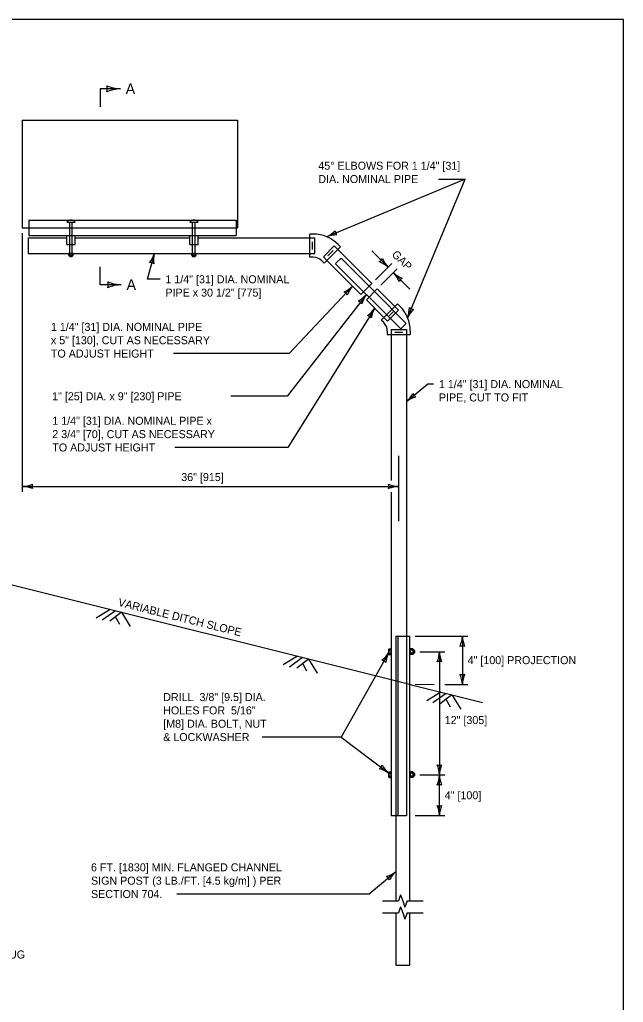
# Model space of a CAD drawing. Extents: x 49991.4 to 50021, y 49987.6 to 50011.4.
# Drawn here: x 50004.09 to 50008.61, y 50003.9 to 50011.26 of the extents above; entities that cross this region are included whole.
import ezdxf

# ---------------------------------------------------------------- set-up
doc = ezdxf.new("R2010")
doc.units = 0
for name, color, linetype in [('Level 1', 7, 'Continuous'), ('Level 2', 7, 'Continuous'), ('Level 3', 7, 'Continuous'), ('Level 4', 7, 'Continuous'), ('Level 5', 7, 'Continuous'), ('Level 6', 7, 'Continuous')]:
    doc.layers.add(name, color=color, linetype=linetype)

msp = doc.modelspace()

# ---------------------------------------------------------------- linework, layer by layer
at = {"layer": 'Level 1'}
for p, q in [((50004.1085, 50010.5093), (50004.1085, 50009.7029)), ((50004.1085, 50010.5093), (50005.7213, 50010.5093)), ((50005.7213, 50010.5093), (50005.7213, 50009.7029)), ((50004.1085, 50009.7029), (50005.7213, 50009.7029)), ((50004.1564, 50009.7029), (50004.1564, 50009.6453)), ((50004.4424, 50009.7455), (50004.5041, 50009.7455)), ((50005.364, 50009.7455), (50005.4257, 50009.7455)), ((50005.7116, 50009.7029), (50005.7116, 50009.6453)), ((50004.1517, 50009.6262), (50004.1517, 50009.511)), ((50004.1517, 50009.6262), (50004.442, 50009.6262)), ((50004.1564, 50009.6453), (50005.7116, 50009.6453)), ((50004.442, 50009.5782), (50004.442, 50009.6453)), ((50004.5045, 50009.5782), (50004.5045, 50009.6453)), ((50004.5045, 50009.6262), (50005.3637, 50009.6262)), ((50005.3637, 50009.5782), (50005.3637, 50009.6453)), ((50005.4261, 50009.5782), (50005.4261, 50009.6453)), ((50005.4261, 50009.6262), (50006.2641, 50009.6262)), ((50006.2641, 50009.4822), (50006.2641, 50009.655)), ((50006.2902, 50009.655), (50006.2641, 50009.655)), ((50004.442, 50009.5782), (50004.5045, 50009.5782)), ((50005.3637, 50009.5782), (50005.4261, 50009.5782)), ((50006.3722, 50009.4374), (50006.4943, 50009.5597)), ((50006.4739, 50009.5393), (50006.7285, 50009.2847)), ((50006.4757, 50009.5782), (50006.4943, 50009.5597)), ((50004.1517, 50009.511), (50006.2641, 50009.511)), ((50004.4566, 50009.4953), (50004.4566, 50009.5106)), ((50004.4899, 50009.5106), (50004.4566, 50009.5106)), ((50004.4566, 50009.4953), (50004.4589, 50009.4939)), ((50004.4589, 50009.5106), (50004.4589, 50009.511)), ((50004.4732, 50009.511), (50004.4589, 50009.511)), ((50004.4876, 50009.4939), (50004.4589, 50009.4939)), ((50004.4637, 50009.511), (50004.4637, 50009.5123)), ((50004.4637, 50009.4867), (50004.4637, 50009.4939)), ((50004.4829, 50009.4891), (50004.4637, 50009.4891)), ((50004.4637, 50009.4867), (50004.466, 50009.4843)), ((50004.4649, 50009.4951), (50004.4649, 50009.5106)), ((50004.4804, 50009.4915), (50004.466, 50009.4915)), ((50004.4804, 50009.4867), (50004.466, 50009.4867)), ((50004.4804, 50009.4843), (50004.466, 50009.4843)), ((50004.4732, 50009.511), (50004.4732, 50009.511)), ((50004.4876, 50009.511), (50004.4732, 50009.511)), ((50004.4829, 50009.4867), (50004.4804, 50009.4843)), ((50004.4817, 50009.4951), (50004.4817, 50009.5106)), ((50004.4829, 50009.511), (50004.4829, 50009.5123)), ((50004.4829, 50009.4867), (50004.4829, 50009.4939)), ((50004.4876, 50009.5106), (50004.4876, 50009.511)), ((50004.4899, 50009.4953), (50004.4876, 50009.4939)), ((50004.4899, 50009.4953), (50004.4899, 50009.5106)), ((50005.3782, 50009.4953), (50005.3782, 50009.5106)), ((50005.4115, 50009.5106), (50005.3782, 50009.5106)), ((50005.3782, 50009.4953), (50005.3805, 50009.4939)), ((50005.3805, 50009.5106), (50005.3805, 50009.511)), ((50005.3948, 50009.511), (50005.3805, 50009.511)), ((50005.4092, 50009.4939), (50005.3805, 50009.4939)), ((50005.3853, 50009.511), (50005.3853, 50009.5123)), ((50005.3853, 50009.4867), (50005.3853, 50009.4939)), ((50005.4045, 50009.4891), (50005.3853, 50009.4891)), ((50005.3853, 50009.4867), (50005.3876, 50009.4843)), ((50005.3865, 50009.4951), (50005.3865, 50009.5106)), ((50005.402, 50009.4915), (50005.3876, 50009.4915)), ((50005.402, 50009.4867), (50005.3876, 50009.4867)), ((50005.402, 50009.4843), (50005.3876, 50009.4843)), ((50005.3948, 50009.511), (50005.3948, 50009.511)), ((50005.4092, 50009.511), (50005.3948, 50009.511)), ((50005.4045, 50009.4867), (50005.402, 50009.4843)), ((50005.4033, 50009.4951), (50005.4033, 50009.5106)), ((50005.4045, 50009.511), (50005.4045, 50009.5123)), ((50005.4045, 50009.4867), (50005.4045, 50009.4939)), ((50005.4092, 50009.5106), (50005.4092, 50009.511)), ((50005.4115, 50009.4953), (50005.4092, 50009.4939)), ((50005.4115, 50009.4953), (50005.4115, 50009.5106)), ((50006.2902, 50009.4822), (50006.2641, 50009.4822)), ((50006.3536, 50009.456), (50006.3722, 50009.4374)), ((50006.3926, 50009.4578), (50006.6471, 50009.2033)), ((50006.6471, 50009.2033), (50006.7285, 50009.2847)), ((50006.6878, 50009.1626), (50006.7692, 50009.2439)), ((50006.7082, 50009.2644), (50006.7489, 50009.2237)), ((50006.7692, 50009.2439), (50006.9016, 50009.1117)), ((50006.6674, 50009.2236), (50006.7082, 50009.183)), ((50006.6878, 50009.1626), (50006.8201, 50009.0302)), ((50006.7997, 50009.0098), (50006.922, 50009.1321)), ((50006.9405, 50009.1135), (50006.922, 50009.1321)), ((50006.8183, 50008.9913), (50006.7997, 50009.0098)), ((50006.8445, 50008.928), (50006.8445, 50008.9018)), ((50006.8445, 50008.9018), (50007.0173, 50008.9018)), ((50006.8733, 50008.9018), (50006.8733, 50007.8069)), ((50006.9885, 50008.9018), (50006.9885, 50006.6729)), ((50007.0173, 50008.928), (50007.0173, 50008.9018)), ((50006.8733, 50007.7205), (50006.8733, 50006.315)), ((50003.7136, 50007.1049), (50007.0128, 50006.2801)), ((50004.7673, 50006.8415), (50004.6622, 50006.7767)), ((50004.807, 50006.8316), (50004.7076, 50006.7607)), ((50004.8511, 50006.8205), (50004.7634, 50006.7529)), ((50004.8511, 50006.8205), (50004.9168, 50006.7139)), ((50004.8391, 50006.7284), (50004.8072, 50006.7867)), ((50006.9885, 50006.6729), (50006.9885, 50006.6401)), ((50006.9086, 50006.6401), (50007.0128, 50006.6401)), ((50006.9086, 50006.6401), (50006.9086, 50006.3062)), ((50006.923, 50006.6401), (50006.923, 50006.3026)), ((50007.0128, 50006.2801), (50007.0128, 50006.6401)), ((50006.8582, 50006.5457), (50006.8565, 50006.5429)), ((50006.8565, 50006.507), (50006.8565, 50006.5429)), ((50006.8582, 50006.5041), (50006.8565, 50006.507)), ((50006.8581, 50006.5354), (50006.8733, 50006.5354)), ((50006.8581, 50006.5144), (50006.8733, 50006.5144)), ((50006.8582, 50006.5457), (50006.8733, 50006.5457)), ((50006.8733, 50006.5249), (50006.8733, 50006.5457)), ((50006.8733, 50006.5369), (50006.875, 50006.5369)), ((50006.8733, 50006.5249), (50006.8733, 50006.5249)), ((50006.8733, 50006.5041), (50006.8733, 50006.5249)), ((50006.8733, 50006.5129), (50006.875, 50006.5129)), ((50007.0128, 50006.5369), (50007.0111, 50006.5369)), ((50007.0128, 50006.5129), (50007.0111, 50006.5129)), ((50007.0128, 50006.5489), (50007.0167, 50006.5489)), ((50007.0128, 50006.5489), (50007.0128, 50006.5249)), ((50007.0128, 50006.5249), (50007.0128, 50006.5249)), ((50007.0128, 50006.5249), (50007.0128, 50006.5009)), ((50007.0167, 50006.5489), (50007.0167, 50006.5457)), ((50007.0167, 50006.5457), (50007.0167, 50006.5041)), ((50007.0172, 50006.5429), (50007.0167, 50006.5429)), ((50007.0167, 50006.5249), (50007.0167, 50006.5249)), ((50007.0172, 50006.507), (50007.0167, 50006.507)), ((50007.0364, 50006.5457), (50007.0172, 50006.5457)), ((50007.0172, 50006.5457), (50007.0172, 50006.5041)), ((50007.0364, 50006.5354), (50007.0172, 50006.5354)), ((50007.0364, 50006.5144), (50007.0172, 50006.5144)), ((50007.0364, 50006.5457), (50007.0381, 50006.5429)), ((50007.0364, 50006.5041), (50007.0381, 50006.507)), ((50007.0381, 50006.5429), (50007.0381, 50006.507)), ((50007.047, 50006.5369), (50007.0381, 50006.5369)), ((50007.047, 50006.5129), (50007.0381, 50006.5129)), ((50007.041, 50006.5339), (50007.041, 50006.5159)), ((50007.044, 50006.5369), (50007.044, 50006.5129)), ((50007.047, 50006.5369), (50007.05, 50006.5339)), ((50007.047, 50006.5339), (50007.047, 50006.5159)), ((50007.047, 50006.5129), (50007.05, 50006.5159)), ((50007.05, 50006.5339), (50007.05, 50006.5159)), ((50006.1705, 50006.4907), (50006.0653, 50006.4259)), ((50006.2102, 50006.4807), (50006.1108, 50006.4099)), ((50006.2542, 50006.4698), (50006.1666, 50006.4022)), ((50006.2423, 50006.3777), (50006.2104, 50006.4359)), ((50006.2542, 50006.4698), (50006.32, 50006.3631)), ((50006.8582, 50006.5041), (50006.8733, 50006.5041)), ((50007.0128, 50006.5009), (50007.0167, 50006.5009)), ((50007.0167, 50006.5041), (50007.0167, 50006.5009)), ((50007.0364, 50006.5041), (50007.0172, 50006.5041)), ((50007.0128, 50006.2801), (50007.0255, 50006.277)), ((50007.0255, 50006.277), (50007.5584, 50006.1437)), ((50007.2459, 50006.2218), (50007.1408, 50006.157)), ((50007.2856, 50006.2119), (50007.1862, 50006.1411)), ((50007.3297, 50006.2009), (50007.242, 50006.1333)), ((50007.3177, 50006.1089), (50007.2858, 50006.1671)), ((50007.3297, 50006.2009), (50007.3954, 50006.0943)), ((50006.8582, 50005.624), (50006.8565, 50005.6212)), ((50006.8565, 50005.5854), (50006.8565, 50005.6212)), ((50006.8582, 50005.624), (50006.8733, 50005.624)), ((50006.8733, 50005.6033), (50006.8733, 50005.624)), ((50007.0128, 50005.6273), (50007.0167, 50005.6273)), ((50007.0128, 50005.6273), (50007.0128, 50005.6033)), ((50007.0167, 50005.6273), (50007.0167, 50005.6241)), ((50007.0167, 50005.6241), (50007.0167, 50005.5825)), ((50007.0172, 50005.6213), (50007.0167, 50005.6213)), ((50007.0364, 50005.6241), (50007.0172, 50005.6241)), ((50007.0172, 50005.6241), (50007.0172, 50005.5825)), ((50007.0364, 50005.6241), (50007.0381, 50005.6213)), ((50007.0381, 50005.6213), (50007.0381, 50005.5854)), ((50006.8582, 50005.5825), (50006.8565, 50005.5854)), ((50006.8581, 50005.6138), (50006.8733, 50005.6138)), ((50006.8581, 50005.5928), (50006.8733, 50005.5928)), ((50006.8582, 50005.5825), (50006.8733, 50005.5825)), ((50006.8733, 50005.6153), (50006.875, 50005.6153)), ((50006.8733, 50005.6033), (50006.8733, 50005.6033)), ((50006.8733, 50005.5825), (50006.8733, 50005.6033)), ((50006.8733, 50005.5913), (50006.875, 50005.5913)), ((50007.0128, 50005.6153), (50007.0111, 50005.6153)), ((50007.0128, 50005.5913), (50007.0111, 50005.5913)), ((50007.0128, 50005.6033), (50007.0128, 50005.6033)), ((50007.0128, 50005.6033), (50007.0128, 50005.5793)), ((50007.0128, 50005.5793), (50007.0167, 50005.5793)), ((50007.0167, 50005.6033), (50007.0167, 50005.6033)), ((50007.0172, 50005.5854), (50007.0167, 50005.5854)), ((50007.0167, 50005.5825), (50007.0167, 50005.5793)), ((50007.0364, 50005.6138), (50007.0172, 50005.6138)), ((50007.0364, 50005.5928), (50007.0172, 50005.5928)), ((50007.0364, 50005.5825), (50007.0172, 50005.5825)), ((50007.0364, 50005.5825), (50007.0381, 50005.5854)), ((50007.047, 50005.6153), (50007.0381, 50005.6153)), ((50007.047, 50005.5913), (50007.0381, 50005.5913)), ((50007.041, 50005.6123), (50007.041, 50005.5943)), ((50007.044, 50005.6153), (50007.044, 50005.5913)), ((50007.047, 50005.6153), (50007.05, 50005.6123)), ((50007.047, 50005.6123), (50007.047, 50005.5943)), ((50007.047, 50005.5913), (50007.05, 50005.5943)), ((50007.05, 50005.6123), (50007.05, 50005.5943))]:
    msp.add_line(p, q, dxfattribs=at)
msp.add_lwpolyline([(50008.6146, 50011.2628), (50000.3356, 50011.2628), (50000.3356, 50000.0624), (50008.6146, 50000.0624)], close=True, dxfattribs=at)
for centre, radius, start, end in [((50004.4732, 50009.7214), 0.0392, 38.02497, 141.97503), ((50005.3949, 50009.7214), 0.0392, 38.02497, 141.97503), ((50006.2903, 50009.3927), 0.2623, 45, 90), ((50004.4608, 50009.5011), 0.0072, 234.6726, 304.40523), ((50004.4733, 50009.5227), 0.0288, 253.01489, 286.97814), ((50004.4857, 50009.5011), 0.0072, 235.59477, 305.17175), ((50005.3824, 50009.5011), 0.0072, 234.6726, 304.40523), ((50005.3949, 50009.5227), 0.0288, 253.01489, 286.97814), ((50005.4073, 50009.5011), 0.0072, 235.59477, 305.17175), ((50006.2903, 50009.3927), 0.0895, 45, 90), ((50006.755, 50008.928), 0.2623, 0, 45), ((50006.755, 50008.928), 0.0895, 0, 45), ((50006.8655, 50006.5405), 0.009, 144.6726, 214.40523), ((50006.8925, 50006.5249), 0.036, 163.01489, 196.97814), ((50006.8655, 50006.5093), 0.009, 145.59477, 215.17175), ((50007.029, 50006.5405), 0.009, 325.59477, 35.17175), ((50007.002, 50006.5249), 0.036, 343.01489, 16.97814), ((50007.029, 50006.5093), 0.009, 324.6726, 34.40523), ((50006.8655, 50005.6189), 0.009, 144.6726, 214.40523), ((50007.029, 50005.6189), 0.009, 325.59477, 35.17175), ((50006.8925, 50005.6033), 0.036, 163.01489, 196.97814), ((50006.8655, 50005.5877), 0.009, 145.59477, 215.17175), ((50007.002, 50005.6033), 0.036, 343.01489, 16.97814), ((50007.029, 50005.5877), 0.009, 324.6726, 34.40523)]:
    msp.add_arc(centre, radius, start, end, dxfattribs=at)
at = {"layer": 'Level 3'}
for p, q in [((50007.4278, 50010.0678), (50006.3907, 50009.635)), ((50006.9973, 50009.0284), (50007.4278, 50010.0678)), ((50007.2289, 50010.0678), (50007.4278, 50010.0678)), ((50004.1085, 50009.6629), (50004.1085, 50007.7237)), ((50006.8506, 50009.4069), (50006.728, 50009.5295)), ((50005.0463, 50009.3166), (50005.0983, 50009.511)), ((50006.7567, 50009.3131), (50006.8789, 50009.4352)), ((50006.7975, 50009.2722), (50006.9197, 50009.3944)), ((50005.1412, 50009.3166), (50005.0463, 50009.3166)), ((50007.014, 50009.2435), (50006.8914, 50009.3661)), ((50006.5845, 50009.2659), (50006.108, 50008.7597)), ((50006.6878, 50009.2033), (50006.095, 50008.4396)), ((50006.7503, 50009.1), (50006.1002, 50008.0557)), ((50006.108, 50008.7597), (50005.2411, 50008.7597)), ((50007.1487, 50008.5307), (50006.9885, 50008.3987)), ((50007.192, 50008.5307), (50007.1487, 50008.5307)), ((50006.095, 50008.4396), (50005.673, 50008.4396)), ((50006.1002, 50008.0557), (50005.2515, 50008.0557)), ((50004.1085, 50007.7637), (50006.9309, 50007.7637)), ((50007.0528, 50006.6401), (50007.4475, 50006.6401)), ((50007.4075, 50006.6401), (50007.4075, 50006.28)), ((50006.8565, 50006.5188), (50006.4999, 50005.8847)), ((50007.09, 50006.5242), (50007.2755, 50006.5242)), ((50007.2355, 50006.5242), (50007.2355, 50005.6009)), ((50007.0528, 50006.2801), (50007.1955, 50006.28)), ((50007.2755, 50006.28), (50007.4475, 50006.28)), ((50006.4999, 50005.8847), (50005.9058, 50005.8847)), ((50006.4999, 50005.8847), (50006.8565, 50005.6148)), ((50007.09, 50005.6009), (50007.2755, 50005.6009)), ((50007.2355, 50005.2961), (50007.2355, 50005.6009)), ((50007.0528, 50005.2961), (50007.2755, 50005.2961)), ((50006.9086, 50004.8754), (50006.7083, 50004.7082)), ((50006.7083, 50004.7082), (50005.2679, 50004.7082))]:
    msp.add_line(p, q, dxfattribs=at)
for centre, radius, start, end in [((50004.8556, 50011.0408), 0.2964, 247.45601, 267.63952), ((50004.6724, 50010.7446), 0.073, 342.13882, 17.86118), ((50004.8587, 50010.4343), 0.3107, 92.82731, 112.07716), ((50006.2905, 50009.8453), 0.233, 295.47894, 314.72879), ((50006.509, 50009.6844), 0.0548, 184.79045, 220.51281), ((50006.4678, 50009.4265), 0.2223, 90.10764, 110.29115), ((50004.886, 50009.5772), 0.2223, 322.48314, 342.66664), ((50005.326, 50009.462), 0.233, 167.85444, 187.10429), ((50006.7599, 50009.4975), 0.0548, 297.17386, 332.89623), ((50007.014, 50009.5576), 0.2223, 202.49106, 222.67456), ((50005.0651, 50009.3871), 0.0548, 57.16594, 92.88831), ((50006.6943, 50009.2341), 0.233, 47.86236, 67.11221), ((50006.7278, 50009.2155), 0.2223, 22.45601, 42.63952), ((50007.0478, 50009.5388), 0.233, 227.82731, 247.07716), ((50006.9821, 50009.2755), 0.0548, 117.13882, 152.86118), ((50004.8622, 50009.572), 0.2964, 247.45601, 267.63952), ((50004.679, 50009.2758), 0.073, 342.13882, 17.86118), ((50004.8653, 50008.9655), 0.3107, 92.82731, 112.07716), ((50006.4278, 50009.4235), 0.2223, 294.66093, 314.84444), ((50006.7631, 50009.1162), 0.233, 140.03223, 159.28208), ((50006.4974, 50009.1718), 0.0548, 29.34374, 65.0661), ((50006.5184, 50009.3472), 0.2223, 299.47187, 319.65538), ((50006.8783, 50009.0691), 0.233, 144.84317, 164.09302), ((50006.6089, 50009.1022), 0.0548, 34.15468, 69.87704), ((50006.5658, 50009.224), 0.2223, 305.91704, 326.10055), ((50006.9547, 50008.9881), 0.233, 151.28834, 170.53819), ((50006.7779, 50009.1069), 0.233, 340.32889, 359.57874), ((50007.199, 50008.935), 0.2223, 134.95759, 155.1411), ((50007.0464, 50009.1469), 0.0548, 229.6404, 265.36276), ((50006.6833, 50008.9908), 0.0548, 40.59985, 76.32221), ((50006.8316, 50008.571), 0.233, 312.31816, 331.56801), ((50007.1227, 50008.2214), 0.2223, 106.94686, 127.13036), ((50007.0874, 50008.4802), 0.0548, 201.62966, 237.35203), ((50004.097, 50007.9964), 0.233, 272.82731, 292.07716), ((50004.0993, 50007.5416), 0.2223, 67.45601, 87.63952), ((50004.2367, 50007.7637), 0.0548, 162.13882, 197.86118), ((50006.9401, 50007.9858), 0.2223, 247.45601, 267.63952), ((50006.8027, 50007.7637), 0.0548, 342.13882, 17.86118), ((50006.9424, 50007.531), 0.233, 92.82731, 112.07716), ((50007.1854, 50006.6493), 0.2223, 337.45601, 357.63952), ((50007.6402, 50006.6516), 0.233, 182.82731, 202.07716), ((50006.6674, 50006.6356), 0.2223, 308.10004, 328.28355), ((50007.065, 50006.4147), 0.233, 153.47134, 172.72119), ((50007.0134, 50006.5334), 0.2223, 337.45601, 357.63952), ((50007.4682, 50006.5357), 0.233, 182.82731, 202.07716), ((50007.4075, 50006.5119), 0.0548, 72.13882, 107.86118), ((50006.7936, 50006.407), 0.0548, 42.78285, 78.50521), ((50007.2355, 50006.396), 0.0548, 72.13882, 107.86118), ((50007.4075, 50006.4082), 0.0548, 252.13882, 287.86118), ((50007.1748, 50006.2685), 0.233, 2.82731, 22.07716), ((50007.6296, 50006.2709), 0.2223, 157.45601, 177.63952), ((50006.7543, 50005.6921), 0.0548, 305.02021, 340.74257), ((50006.7252, 50005.4223), 0.233, 55.7087, 74.95855), ((50006.9979, 50005.7864), 0.2223, 210.3374, 230.52091), ((50007.2355, 50005.7291), 0.0548, 252.13882, 287.86118), ((50007.0028, 50005.5894), 0.233, 2.82731, 22.07716), ((50007.4576, 50005.5917), 0.2223, 157.45601, 177.63952), ((50007.0134, 50005.6101), 0.2223, 337.45601, 357.63952), ((50007.4682, 50005.6124), 0.233, 182.82731, 202.07716), ((50007.2355, 50005.4727), 0.0548, 72.13882, 107.86118), ((50007.2355, 50005.4243), 0.0548, 252.13882, 287.86118), ((50007.0028, 50005.2846), 0.233, 2.82731, 22.07716), ((50007.4576, 50005.2869), 0.2223, 157.45601, 177.63952), ((50006.7733, 50005.0518), 0.2223, 287.30393, 307.48744), ((50006.8102, 50004.7932), 0.0548, 21.98674, 57.7091), ((50007.0665, 50004.7041), 0.233, 132.67523, 151.92508)]:
    msp.add_arc(centre, radius, start, end, dxfattribs=at)
at = {"layer": 'Level 4'}
for p, q in [((50004.1564, 50009.7605), (50004.1564, 50009.7029)), ((50004.1564, 50009.7605), (50005.7116, 50009.7605)), ((50005.7116, 50009.7605), (50005.7116, 50009.7029)), ((50004.4636, 50009.511), (50004.4636, 50009.7455)), ((50004.4829, 50009.511), (50004.4829, 50009.7455)), ((50005.3853, 50009.511), (50005.3853, 50009.7455)), ((50005.4045, 50009.511), (50005.4045, 50009.7455)), ((50006.2641, 50009.6262), (50006.3025, 50009.6262)), ((50006.3025, 50009.511), (50006.3025, 50009.6262)), ((50006.2832, 50009.5398), (50006.2832, 50009.5974)), ((50006.3654, 50009.4851), (50006.4468, 50009.5665)), ((50006.3993, 50009.4918), (50006.44, 50009.5326)), ((50006.4468, 50009.5665), (50006.4739, 50009.5393)), ((50006.2641, 50009.511), (50006.3025, 50009.511)), ((50006.3654, 50009.4851), (50006.3926, 50009.4578)), ((50006.4572, 50009.4339), (50006.4981, 50009.4745)), ((50006.498, 50009.4744), (50006.7082, 50009.2644)), ((50006.4566, 50009.4333), (50006.6674, 50009.2236)), ((50006.7082, 50009.183), (50006.9467, 50008.9456)), ((50006.7489, 50009.2237), (50006.9869, 50008.9858)), ((50006.8472, 50009.0029), (50006.9289, 50009.0846)), ((50006.9016, 50009.1117), (50006.9289, 50009.0846)), ((50006.8201, 50009.0302), (50006.8472, 50009.0029)), ((50006.8591, 50009.0421), (50006.8897, 50009.0727)), ((50006.8733, 50008.9403), (50006.8733, 50008.9018)), ((50006.8733, 50008.9403), (50006.9885, 50008.9403)), ((50006.9467, 50008.9456), (50006.9869, 50008.9858)), ((50006.9885, 50008.9403), (50006.9885, 50008.9018)), ((50006.9021, 50008.921), (50006.9597, 50008.921)), ((50006.9885, 50006.6401), (50006.9885, 50005.2961)), ((50006.8733, 50006.315), (50006.8733, 50005.2961)), ((50006.9086, 50006.3062), (50006.9086, 50004.6563)), ((50006.923, 50006.3026), (50006.923, 50005.2961)), ((50007.0128, 50004.6563), (50007.0128, 50006.2801)), ((50006.8733, 50005.2961), (50006.9885, 50005.2961)), ((50006.9086, 50004.5666), (50006.9086, 50004.1736)), ((50007.0128, 50004.1736), (50007.0128, 50004.5666)), ((50006.9086, 50004.1736), (50007.0128, 50004.1736))]:
    msp.add_line(p, q, dxfattribs=at)
at = {"layer": 'Level 5'}
msp.add_line((50006.9309, 50007.5021), (50006.9309, 50007.9941), dxfattribs=at)
at = {"layer": 'Level 6'}
for p, q in [((50004.8434, 50010.7446), (50004.6928, 50010.7446)), ((50004.6928, 50010.7446), (50004.6928, 50010.6093)), ((50004.6928, 50009.2758), (50004.6926, 50009.411)), ((50004.85, 50009.2758), (50004.6928, 50009.2758)), ((50006.9445, 50004.702), (50006.9283, 50004.6563)), ((50006.9445, 50004.702), (50006.9607, 50004.6563)), ((50006.8086, 50004.6563), (50006.9283, 50004.6563)), ((50006.9445, 50004.6123), (50006.9283, 50004.5666)), ((50006.9445, 50004.6123), (50006.9607, 50004.5666)), ((50006.9607, 50004.6563), (50006.9769, 50004.6106)), ((50006.9931, 50004.6563), (50006.9769, 50004.6106)), ((50006.9931, 50004.6563), (50007.1128, 50004.6563)), ((50006.8086, 50004.5666), (50006.9283, 50004.5666)), ((50006.9607, 50004.5666), (50006.9769, 50004.5209)), ((50006.9931, 50004.5666), (50006.9769, 50004.5209)), ((50006.9931, 50004.5666), (50007.1128, 50004.5666))]:
    msp.add_line(p, q, dxfattribs=at)

# ---------------------------------------------------------------- texts
at = {"layer": 'Level 2'}
for s, height, p in [('A', 0.08, (50004.8834, 50010.7046)), ('45° ELBOWS FOR 1 1/4" [31]', 0.06, (50006.3279, 50010.1378)), ('DIA. NOMINAL PIPE', 0.06, (50006.3279, 50010.0378)), ('A', 0.08, (50004.89, 50009.2358)), ('1 1/4" [31] DIA. NOMINAL', 0.06, (50005.1812, 50009.2866)), ('PIPE x 30 1/2" [775]', 0.06, (50005.1812, 50009.1866)), ('1 1/4" [31] DIA. NOMINAL PIPE', 0.06, (50004.3228, 50008.9297)), ('x 5" [130], CUT AS NECESSARY ', 0.06, (50004.3228, 50008.8297)), ('TO ADJUST HEIGHT', 0.06, (50004.3228, 50008.7297)), ('1 1/4" [31] DIA. NOMINAL', 0.06, (50007.232, 50008.5007)), ('1" [25] DIA. x 9" [230] PIPE', 0.06, (50004.3319, 50008.4096)), ('PIPE, CUT TO FIT', 0.06, (50007.232, 50008.4007)), ('1 1/4" [31] DIA. NOMINAL PIPE x', 0.06, (50004.3332, 50008.2257)), ('2 3/4" [70], CUT AS NECESSARY', 0.06, (50004.3332, 50008.1257)), ('TO ADJUST HEIGHT', 0.06, (50004.3332, 50008.0257)), ('36" [915]', 0.06, (50005.3001, 50007.8037)), ('4" [100] PROJECTION', 0.06, (50007.4475, 50006.4314)), ('DRILL  3/8" [9.5] DIA.', 0.06, (50005.1648, 50006.1547)), ('HOLES FOR  5/16"', 0.06, (50005.1648, 50006.0547)), ('[M8] DIA. BOLT, NUT', 0.06, (50005.1648, 50005.9547)), ('12" [305]', 0.06, (50007.2755, 50005.9822)), ('& LOCKWASHER', 0.06, (50005.1648, 50005.8547)), ('4" [100]', 0.06, (50007.2755, 50005.4185)), ('6 FT. [1830] MIN. FLANGED CHANNEL', 0.06, (50004.6235, 50004.8782)), ('SIGN POST (3 LB./FT. [4.5 kg/m] ) PER', 0.06, (50004.6235, 50004.7782)), ('SECTION 704.', 0.06, (50004.6235, 50004.6782)), ('FILLER, CUT TO FIT SNUG', 0.06, (50003.1171, 50004.2247))]:
    msp.add_text(s, height=height, dxfattribs=at).set_placement(p)
for s, rotation, p in [('GAP', 315.02143, (50006.8737, 50009.4976)), ('VARIABLE DITCH SLOPE', 345.96425, (50004.8227, 50006.8689))]:
    msp.add_text(s, height=0.06, rotation=rotation, dxfattribs=at).set_placement(p)

doc.saveas('drawing.dxf')
